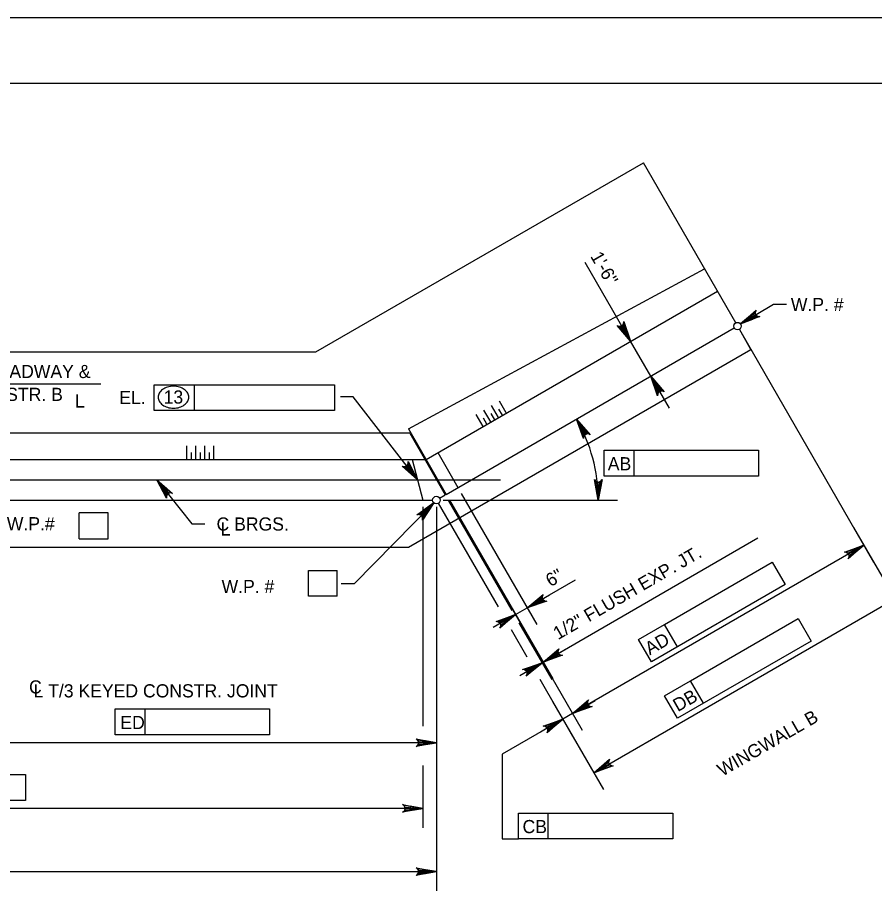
# Model space of a CAD drawing. Extents: x 638340 to 640242, y 295465 to 298435.
# Drawn here: x 638762.3 to 638957.8, y 298235.5 to 298435.5 of the extents above; entities that cross this region are included whole.
import ezdxf

# ---------------------------------------------------------------- set-up
doc = ezdxf.new("R2010")
doc.units = 0
for name, color, linetype in [('2', 7, 'Continuous'), ('Level 10', 7, 'Continuous'), ('Level 2', 7, 'Continuous'), ('Level 3', 7, 'Continuous'), ('PLT-BNDY', 7, 'Continuous')]:
    doc.layers.add(name, color=color, linetype=linetype)

msp = doc.modelspace()

# ---------------------------------------------------------------- linework, layer by layer
at = {"layer": '2'}
msp.add_line((638475.46, 298420.46), (639261.46, 298420.46), dxfattribs=at)
at = {"layer": 'Level 10'}
for p, q in [((638830.41, 298359.21), (638905.1, 298402.33)), ((638926.17, 298365.85), (638905.1, 298402.33)), ((638851.52, 298341.64), (638919.07, 298378.13)), ((638855.52, 298334.71), (638921.99, 298373.09)), ((638860.12, 298326.74), (638925.86, 298364.69)), ((638929.66, 298359.79), (638927.02, 298364.38)), ((638656.5, 298359.21), (638830.41, 298359.21)), ((638851.55, 298314.7), (638929.66, 298359.79)), ((638851.79, 298340.66), (638636.04, 298340.74)), ((638851.52, 298341.64), (638860.12, 298326.74)), ((638851.79, 298340.66), (638859.9, 298326.61)), ((638858.18, 298336.25), (638862.78, 298328.27)), ((638632.53, 298334.65), (638855.26, 298334.65)), ((638852.34, 298334.65), (638854.81, 298325.44)), ((638607.82, 298330.05), (638872.51, 298330.05)), ((638858.62, 298325.87), (638859.9, 298326.61)), ((638742.3, 298325.44), (638857.03, 298325.44)), ((638632.3, 298314.7), (638851.55, 298314.7))]:
    msp.add_line(p, q, dxfattribs=at)
at = {"layer": 'Level 2'}
for p, q in [((638873.84, 298345.29), (638872.26, 298348.02)), ((638870.29, 298343.24), (638868.71, 298345.97)), ((638872.06, 298344.26), (638870.49, 298346.99)), ((638872.95, 298344.78), (638872.14, 298346.18)), ((638868.52, 298342.22), (638866.94, 298344.95)), ((638869.4, 298342.73), (638868.6, 298344.13)), ((638871.18, 298343.75), (638870.37, 298345.15)), ((638800.97, 298334.65), (638800.97, 298337.81)), ((638801.99, 298334.65), (638801.99, 298336.27)), ((638803.01, 298334.65), (638803.01, 298337.81)), ((638804.04, 298334.65), (638804.04, 298336.27)), ((638805.06, 298334.65), (638805.06, 298337.81)), ((638806.08, 298334.65), (638806.08, 298336.27)), ((638807.11, 298334.65), (638807.11, 298337.81))]:
    msp.add_line(p, q, dxfattribs=at)
at = {"layer": 'Level 3'}
for p, q in [((638900.72, 298364.21), (638891.83, 298379.62)), ((638927.27, 298365.61), (638934.79, 298370.12)), ((638934.79, 298370.12), (638937.74, 298370.12)), ((638927.36, 298363.78), (638957.65, 298311.31)), ((638906.8, 298353.68), (638902.19, 298361.66)), ((638749.1, 298351.92), (638781.34, 298351.92)), ((638793.52, 298351.73), (638802.68, 298351.73)), ((638793.52, 298345.84), (638793.52, 298351.73)), ((638802.68, 298345.84), (638802.68, 298351.73)), ((638802.68, 298351.73), (638834.65, 298351.73)), ((638834.65, 298351.73), (638834.65, 298345.84)), ((638908.27, 298351.13), (638911.02, 298346.36)), ((638838.93, 298348.95), (638835.99, 298348.95)), ((638853.58, 298330.05), (638838.93, 298348.95)), ((638834.65, 298345.84), (638793.52, 298345.84)), ((638896.18, 298336.8), (638903.01, 298336.8)), ((638896.18, 298330.9), (638896.18, 298336.8)), ((638903.01, 298330.9), (638903.01, 298336.8)), ((638903.01, 298336.8), (638931.41, 298336.8)), ((638931.41, 298336.8), (638931.41, 298330.9)), ((638794.13, 298330.05), (638802.08, 298319.99)), ((638931.41, 298330.9), (638896.18, 298330.9)), ((638863.55, 298326.94), (638880.82, 298297.03)), ((638857.32, 298324.81), (638839.14, 298306.31)), ((638854.81, 298323.9), (638854.81, 298273.86)), ((638857.88, 298323.9), (638857.88, 298265.67)), ((638858.3, 298324.71), (638871.96, 298301.06)), ((638859.42, 298325.44), (638899.24, 298325.44)), ((638860.67, 298325.28), (638875.13, 298300.23)), ((638860.89, 298325.41), (638891.18, 298272.94)), ((638860.89, 298325.41), (638884.43, 298284.64)), ((638860.89, 298325.41), (638878.17, 298295.49)), ((638776.38, 298316.61), (638776.38, 298322.51)), ((638782.96, 298322.51), (638776.38, 298322.51)), ((638782.96, 298316.61), (638782.96, 298322.51)), ((638802.08, 298319.99), (638805.03, 298319.99)), ((638953.09, 298319.21), (638964.7, 298299.1)), ((638776.38, 298316.61), (638782.96, 298316.61)), ((638882.22, 298288.47), (638931.25, 298316.79)), ((638955.44, 298315.14), (638888.97, 298276.77)), ((638909.92, 298297.06), (638934.52, 298311.26)), ((638934.52, 298311.26), (638937.46, 298306.16)), ((638828.68, 298309.38), (638835.26, 298309.38)), ((638828.68, 298303.49), (638828.68, 298309.38)), ((638835.26, 298303.49), (638835.26, 298309.38)), ((638839.14, 298306.31), (638836.19, 298306.31)), ((638883.72, 298303.8), (638889.65, 298307.23)), ((638937.46, 298306.16), (638906.95, 298288.54)), ((638835.26, 298303.49), (638828.68, 298303.49)), ((638878.61, 298300.85), (638883.72, 298303.8)), ((638893.78, 298263.26), (638962.49, 298302.93)), ((638875.95, 298299.32), (638878.61, 298300.86)), ((638875.95, 298299.32), (638870.85, 298296.37)), ((638915.85, 298284.2), (638940.45, 298298.4)), ((638940.45, 298298.4), (638943.39, 298293.29)), ((638874.93, 298295.91), (638878.52, 298289.68)), ((638876.72, 298297.48), (638884.21, 298284.51)), ((638904, 298293.64), (638909.92, 298297.06)), ((638912.87, 298291.96), (638909.92, 298297.06)), ((638906.95, 298288.54), (638904, 298293.64)), ((638943.39, 298293.29), (638912.88, 298275.68)), ((638884.77, 298289.94), (638887.32, 298291.42)), ((638882, 298288.34), (638876.89, 298285.39)), ((638882, 298288.34), (638882.22, 298288.47)), ((638857.88, 298284.96), (638857.88, 298236.32)), ((638881.45, 298284.62), (638888.94, 298271.64)), ((638909.93, 298280.78), (638915.85, 298284.2)), ((638918.8, 298279.09), (638915.85, 298284.2)), ((638912.88, 298275.68), (638909.93, 298280.78)), ((638884.38, 298279.54), (638895.99, 298259.43)), ((638891.53, 298278.24), (638894.08, 298279.71)), ((638784.57, 298277.81), (638791.4, 298277.81)), ((638784.57, 298271.92), (638784.57, 298277.81)), ((638791.4, 298271.92), (638791.4, 298277.81)), ((638791.4, 298277.81), (638819.8, 298277.81)), ((638819.8, 298277.81), (638819.8, 298271.92)), ((638888.97, 298276.77), (638886.73, 298275.47)), ((638886.73, 298275.47), (638872.89, 298267.48)), ((638884.18, 298274), (638881.63, 298272.53)), ((638819.8, 298271.92), (638784.57, 298271.92)), ((638857.88, 298270.1), (638749.43, 298270.1)), ((638872.89, 298267.48), (638872.89, 298248.17)), ((638854.81, 298264.89), (638854.81, 298250.71)), ((638735.7, 298262.85), (638764.1, 298262.85)), ((638764.1, 298262.85), (638764.1, 298256.95)), ((638764.1, 298256.95), (638728.87, 298256.95)), ((638854.81, 298255.13), (638638.16, 298255.13)), ((638876.59, 298254.06), (638883.42, 298254.06)), ((638876.59, 298248.17), (638876.59, 298254.06)), ((638883.42, 298248.17), (638883.42, 298254.06)), ((638883.42, 298254.06), (638911.83, 298254.06)), ((638911.83, 298254.06), (638911.83, 298248.17)), ((638872.89, 298248.17), (638876.59, 298248.17)), ((638911.83, 298248.17), (638876.59, 298248.17)), ((638630.06, 298240.74), (638857.88, 298240.74))]:
    msp.add_line(p, q, dxfattribs=at)
for points in [[(638927.27, 298365.61), (638930.81, 298368.75), (638930.63, 298368.36), (638930.64, 298368), (638930.75, 298367.7), (638930.96, 298367.46), (638931.28, 298367.29), (638931.71, 298367.26), (638927.27, 298365.61), (638931.28, 298367.29), (638930.96, 298367.46), (638927.27, 298365.61), (638930.75, 298367.7), (638930.64, 298368), (638927.27, 298365.61), (638930.63, 298368.36)], [(638902.19, 298361.66), (638899.11, 298365.25), (638899.51, 298365.07), (638899.87, 298365.06), (638900.17, 298365.17), (638900.41, 298365.37), (638900.59, 298365.69), (638900.62, 298366.12), (638902.19, 298361.66), (638900.59, 298365.69), (638900.41, 298365.37), (638902.19, 298361.66), (638900.17, 298365.17), (638899.87, 298365.06), (638902.19, 298361.66), (638899.51, 298365.07)], [(638906.8, 298353.68), (638909.88, 298350.09), (638909.48, 298350.28), (638909.12, 298350.28), (638908.83, 298350.17), (638908.58, 298349.97), (638908.4, 298349.65), (638908.37, 298349.22), (638906.8, 298353.68), (638908.4, 298349.65), (638908.58, 298349.97), (638906.8, 298353.68), (638908.83, 298350.17), (638909.12, 298350.28), (638906.8, 298353.68), (638909.48, 298350.28)], [(638889.87, 298343.91), (638892.95, 298340.32), (638892.56, 298340.5), (638892.19, 298340.51), (638891.9, 298340.4), (638891.66, 298340.2), (638891.48, 298339.88), (638891.44, 298339.45), (638889.87, 298343.91), (638891.48, 298339.88), (638891.66, 298340.2), (638889.87, 298343.91), (638891.9, 298340.4), (638892.19, 298340.51), (638889.87, 298343.91), (638892.56, 298340.5)], [(638853.58, 298330.05), (638850.04, 298333.19), (638850.46, 298333.06), (638850.82, 298333.1), (638851.1, 298333.25), (638851.31, 298333.48), (638851.44, 298333.82), (638851.42, 298334.26), (638853.58, 298330.05), (638851.44, 298333.82), (638851.31, 298333.48), (638853.58, 298330.05), (638851.1, 298333.25), (638850.82, 298333.1), (638853.58, 298330.05), (638850.46, 298333.06)], [(638794.13, 298330.05), (638797.7, 298326.94), (638797.28, 298327.06), (638796.92, 298327.02), (638796.64, 298326.86), (638796.43, 298326.63), (638796.3, 298326.29), (638796.33, 298325.86), (638794.13, 298330.05), (638796.3, 298326.29), (638796.43, 298326.63), (638794.13, 298330.05), (638796.64, 298326.86), (638796.92, 298327.02), (638794.13, 298330.05), (638797.28, 298327.06)], [(638894.82, 298325.44), (638893.95, 298330.09), (638894.2, 298329.74), (638894.51, 298329.55), (638894.82, 298329.5), (638895.13, 298329.55), (638895.44, 298329.74), (638895.69, 298330.09), (638894.82, 298325.44), (638895.44, 298329.74), (638895.13, 298329.55), (638894.82, 298325.44), (638894.82, 298329.5), (638894.51, 298329.55), (638894.82, 298325.44), (638894.2, 298329.74)], [(638857.32, 298324.81), (638854.68, 298320.88), (638854.75, 298321.31), (638854.66, 298321.66), (638854.48, 298321.91), (638854.22, 298322.09), (638853.87, 298322.18), (638853.44, 298322.1), (638857.32, 298324.81), (638853.87, 298322.18), (638854.22, 298322.09), (638857.32, 298324.81), (638854.48, 298321.91), (638854.66, 298321.66), (638857.32, 298324.81), (638854.75, 298321.31)], [(638955.44, 298315.14), (638951.85, 298312.06), (638952.03, 298312.46), (638952.04, 298312.82), (638951.93, 298313.12), (638951.73, 298313.36), (638951.41, 298313.54), (638950.98, 298313.57), (638955.44, 298315.14), (638951.41, 298313.54), (638951.73, 298313.36), (638955.44, 298315.14), (638951.93, 298313.12), (638952.04, 298312.82), (638955.44, 298315.14), (638952.03, 298312.46)], [(638878.61, 298300.85), (638882.21, 298303.93), (638882.02, 298303.54), (638882.02, 298303.18), (638882.12, 298302.88), (638882.33, 298302.64), (638882.64, 298302.46), (638883.08, 298302.42), (638878.61, 298300.85), (638882.64, 298302.46), (638882.33, 298302.64), (638878.61, 298300.85), (638882.12, 298302.88), (638882.02, 298303.18), (638878.61, 298300.85), (638882.02, 298303.54)], [(638875.95, 298299.32), (638872.36, 298296.24), (638872.55, 298296.63), (638872.55, 298297), (638872.44, 298297.29), (638872.24, 298297.53), (638871.92, 298297.71), (638871.49, 298297.75), (638875.95, 298299.32), (638871.92, 298297.71), (638872.24, 298297.53), (638875.95, 298299.32), (638872.44, 298297.29), (638872.55, 298297), (638875.95, 298299.32), (638872.55, 298296.63)], [(638882.22, 298288.47), (638885.81, 298291.55), (638885.63, 298291.15), (638885.62, 298290.79), (638885.73, 298290.5), (638885.93, 298290.25), (638886.25, 298290.07), (638886.68, 298290.04), (638882.22, 298288.47), (638886.25, 298290.07), (638885.93, 298290.25), (638882.22, 298288.47), (638885.73, 298290.5), (638885.62, 298290.79), (638882.22, 298288.47), (638885.63, 298291.15)], [(638882, 298288.34), (638878.4, 298285.26), (638878.59, 298285.65), (638878.6, 298286.01), (638878.49, 298286.31), (638878.28, 298286.56), (638877.97, 298286.73), (638877.53, 298286.77), (638882, 298288.34), (638877.97, 298286.73), (638878.28, 298286.56), (638882, 298288.34), (638878.49, 298286.31), (638878.6, 298286.01), (638882, 298288.34), (638878.59, 298285.65)], [(638888.97, 298276.77), (638892.57, 298279.85), (638892.38, 298279.45), (638892.38, 298279.09), (638892.49, 298278.8), (638892.69, 298278.55), (638893, 298278.37), (638893.44, 298278.34), (638888.97, 298276.77), (638893, 298278.37), (638892.69, 298278.55), (638888.97, 298276.77), (638892.49, 298278.8), (638892.38, 298279.09), (638888.97, 298276.77), (638892.38, 298279.45)], [(638886.73, 298275.47), (638883.14, 298272.39), (638883.32, 298272.79), (638883.33, 298273.15), (638883.22, 298273.45), (638883.02, 298273.69), (638882.7, 298273.87), (638882.27, 298273.9), (638886.73, 298275.47), (638882.7, 298273.87), (638883.02, 298273.69), (638886.73, 298275.47), (638883.22, 298273.45), (638883.33, 298273.15), (638886.73, 298275.47), (638883.32, 298272.79)], [(638857.88, 298270.1), (638853.23, 298269.22), (638853.59, 298269.47), (638853.77, 298269.78), (638853.83, 298270.1), (638853.77, 298270.41), (638853.59, 298270.72), (638853.23, 298270.97), (638857.88, 298270.1), (638853.59, 298270.72), (638853.77, 298270.41), (638857.88, 298270.1), (638853.83, 298270.1), (638853.77, 298269.78), (638857.88, 298270.1), (638853.59, 298269.47)], [(638893.78, 298263.26), (638897.37, 298266.34), (638897.19, 298265.94), (638897.18, 298265.58), (638897.29, 298265.29), (638897.49, 298265.04), (638897.81, 298264.86), (638898.25, 298264.83), (638893.78, 298263.26), (638897.81, 298264.86), (638897.49, 298265.04), (638893.78, 298263.26), (638897.29, 298265.29), (638897.18, 298265.58), (638893.78, 298263.26), (638897.19, 298265.94)], [(638854.81, 298255.13), (638850.16, 298254.26), (638850.52, 298254.51), (638850.7, 298254.82), (638850.76, 298255.13), (638850.7, 298255.44), (638850.52, 298255.76), (638850.16, 298256), (638854.81, 298255.13), (638850.52, 298255.76), (638850.7, 298255.44), (638854.81, 298255.13), (638850.76, 298255.13), (638850.7, 298254.82), (638854.81, 298255.13), (638850.52, 298254.51)], [(638857.88, 298240.74), (638853.23, 298239.87), (638853.59, 298240.12), (638853.77, 298240.43), (638853.83, 298240.74), (638853.77, 298241.06), (638853.59, 298241.37), (638853.23, 298241.62), (638857.88, 298240.74), (638853.59, 298241.37), (638853.77, 298241.06), (638857.88, 298240.74), (638853.83, 298240.74), (638853.77, 298240.43), (638857.88, 298240.74), (638853.59, 298240.12)]]:
    msp.add_lwpolyline(points, dxfattribs=at)
for points in [[(638930.05, 298366.71), (638929.55, 298367.55), (638927.27, 298365.61)], [(638901.15, 298364.46), (638900.3, 298363.97), (638902.19, 298361.66)], [(638908.7, 298351.38), (638907.85, 298350.88), (638906.8, 298353.68)], [(638851.38, 298332.07), (638852.16, 298332.68), (638853.58, 298330.05)], [(638796.34, 298328.04), (638795.57, 298327.43), (638794.13, 298330.05)], [(638854.9, 298323.05), (638855.6, 298322.36), (638857.32, 298324.81)], [(638952.64, 298314.09), (638953.13, 298313.24), (638955.44, 298315.14)], [(638880.92, 298302.75), (638881.41, 298301.9), (638878.61, 298300.86)], [(638873.16, 298298.27), (638873.65, 298297.42), (638875.95, 298299.32)], [(638884.53, 298290.37), (638885.02, 298289.52), (638882.22, 298288.47)], [(638879.2, 298287.29), (638879.69, 298286.44), (638882, 298288.34)], [(638891.28, 298278.67), (638891.77, 298277.82), (638888.97, 298276.77)], [(638883.93, 298274.42), (638884.42, 298273.57), (638886.73, 298275.47)], [(638854.93, 298270.59), (638854.93, 298269.6), (638857.88, 298270.1)], [(638896.09, 298265.16), (638896.58, 298264.31), (638893.78, 298263.26)], [(638851.86, 298255.62), (638851.86, 298254.64), (638854.81, 298255.13)], [(638854.93, 298241.24), (638854.93, 298240.25), (638857.88, 298240.74)]]:
    msp.add_lwpolyline(points, close=True, dxfattribs=at)
for centre in [(638926.59, 298365.11), (638857.88, 298325.44)]:
    msp.add_circle(centre, 0.849, dxfattribs=at)
for centre, radius, start, end in [((638797.02, 298348.43), 2.75, 125.6316, 149.9767), ((638797.55, 298347.69), 3.65, 106.5358, 125.6316), ((638797.89, 298346.54), 4.86, 90, 106.5358), ((638797.89, 298346.54), 4.86, 73.4642, 90), ((638798.24, 298347.69), 3.65, 54.3684, 73.4642), ((638798.76, 298348.43), 2.75, 30.0233, 54.3684), ((638796.22, 298348.89), 1.82, 149.9767, 180), ((638796.22, 298348.89), 1.82, 180, 210.0233), ((638797.02, 298349.36), 2.75, 210.0233, 234.3684), ((638798.76, 298349.36), 2.75, 305.6316, 329.9767), ((638799.56, 298348.89), 1.82, 0, 30.0233), ((638799.56, 298348.89), 1.82, 329.9767, 0), ((638797.55, 298350.09), 3.65, 234.3684, 253.4642), ((638797.89, 298351.25), 4.86, 253.4642, 270), ((638797.89, 298351.25), 4.86, 270, 286.5358), ((638798.24, 298350.09), 3.65, 286.5358, 305.6316), ((638857.88, 298325.44), 36.94, 0.0011, 30.0006)]:
    msp.add_arc(centre, radius, start, end, dxfattribs=at)
at = {"layer": 'PLT-BNDY'}
msp.add_lwpolyline([(638435.46, 298435.46), (639276.46, 298435.46), (639276.46, 297841.46), (638435.46, 297841.46)], close=True, dxfattribs=at)

# ---------------------------------------------------------------- texts
at = {"layer": 'Level 3'}
for s, height, rotation, p in [('1\'-6"', 3, 299.9871, (638892.92, 298381.03)), ('1/2" FLUSH EXP. JT.', 3.0001, 30.0203, (638885.63, 298293.48)), ('6"', 3, 30.0203, (638883.92, 298305.54)), ('AD', 3, 30, (638906.57, 298290)), ('DB', 3, 30, (638912.96, 298277.07)), ('WINGWALL B', 3, 30, (638923.11, 298262.32))]:
    msp.add_text(s, height=height, rotation=rotation, dxfattribs=at).set_placement(p)
for s, height, p in [('W.P. #', 3, (638938.76, 298368.51)), ('C ROADWAY &', 3.0001, (638750.42, 298353.26)), ('CONSTR. B', 3, (638750.81, 298348.04)), ('EL.', 3, (638785.52, 298347.32)), ('13', 3, (638795.64, 298347.43)), ('L', 3, (638775.43, 298346.52)), ('AB', 3, (638896.99, 298332.22)), ('W.P.#', 3, (638759.87, 298318.54)), ('C BRGS.', 3, (638807.72, 298318.48)), ('L', 3, (638808.66, 298317.35)), ('W.P. #', 3, (638808.87, 298304.23)), ('C', 3, (638764.94, 298281.33)), ('L T/3 KEYED CONSTR. JOINT', 3.0001, (638765.96, 298280.44)), ('ED', 3, (638785.77, 298273.22)), ('CB', 3, (638877.54, 298249.49))]:
    msp.add_text(s, height=height, dxfattribs=at).set_placement(p)

doc.saveas('drawing.dxf')
